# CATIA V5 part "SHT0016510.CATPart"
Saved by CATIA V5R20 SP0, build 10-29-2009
Part number: SHT0016510
Bounding box of the stored display mesh (mm): x 989.999 to 1143.999, y -723.979 to -445.979, z 20 to 150
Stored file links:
  E:\李燕龙\吉利商用车G3\07 设计变更\ECR0009849--标配底支架后移50mm设计变更\数据图纸\SHT0015284 标配前支撑钣金\SHT0016510.CATPart
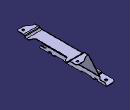
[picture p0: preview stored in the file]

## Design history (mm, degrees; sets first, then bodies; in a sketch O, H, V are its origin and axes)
Body1 (main body)
Body2
  Solid1: solid without history
  Sketch1 on face of Solid1, origin (829.87, 0, -386.7355), H (0, -1, 0), V (0.4224, 0, 0.9064)
    line L1 (482.8534, 576.6256) -> (684.9326, 576.6256)
    line L2 (684.9326, 576.6256) -> (684.9326, 481.4364)
    line L3 (684.9326, 481.4364) -> (482.8534, 481.4364)
    line L4 (482.8534, 481.4364) -> (482.8534, 576.6256)
    horizontal: L1 H, L3 H
    vertical: L2 V, L4 V
  Pad1: profile Sketch1, direction (0.9064, 0, -0.4224), length 2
